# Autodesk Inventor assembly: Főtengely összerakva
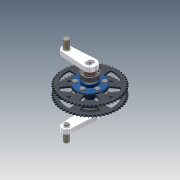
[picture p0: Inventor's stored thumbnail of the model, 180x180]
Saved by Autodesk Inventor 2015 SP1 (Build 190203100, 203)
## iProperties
Created: 2013-02
Part Number: Főtengely összerakva
Document SubType Name: Assembly
Designer: Marci
Author: Marci
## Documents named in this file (12)
- C:\Users\TREINA11\Desktop\#01- Polymechanics and Automation\01 - 3D Models\Pneumatic System\Főtengely összerakva.iam
- C:\Users\TREINA11\Desktop\#01- Polymechanics and Automation\01 - 3D Models\Pneumatic System\Főtengely.ipt
- C:\Users\TREINA11\Desktop\#01- Polymechanics and Automation\01 - 3D Models\Pneumatic System\Szabadonfutó távtartó.ipt
- C:\Users\TREINA11\Desktop\#01- Polymechanics and Automation\01 - 3D Models\Pneumatic System\inafag_hfl3030_elarmg9trzt6j3zc3til76m2w.iam
- C:\Users\TREINA11\Desktop\#01- Polymechanics and Automation\01 - 3D Models\Pneumatic System\DIN 471 - 30 x 1,5(1).ipt
- C:\Users\TREINA11\Desktop\#01- Polymechanics and Automation\01 - 3D Models\Pneumatic System\inafag_6205_1vmsegths975f8cvzct4fnofv.iam
- C:\Users\TREINA11\Desktop\#01- Polymechanics and Automation\01 - 3D Models\Pneumatic System\Sonka távtartó.ipt
- C:\Users\TREINA11\Desktop\#01- Polymechanics and Automation\01 - 3D Models\Pneumatic System\Sonka.ipt
- C:\Users\TREINA11\Desktop\#01- Polymechanics and Automation\01 - 3D Models\Pneumatic System\Csapszeg.ipt
- C:\Users\TREINA11\Desktop\#01- Polymechanics and Automation\01 - 3D Models\Pneumatic System\Csapszeg alátét.ipt
- C:\Users\TREINA11\Desktop\#01- Polymechanics and Automation\01 - 3D Models\Pneumatic System\Lánckerék összerakva.iam
- C:\Users\TREINA11\Desktop\#01- Polymechanics and Automation\01 - 3D Models\Pneumatic System\ISO 4017 - M8 x 16ISO.ipt
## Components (20 placed, 11 different names)
1. Főtengely:1 — Mate:1, Flush:1, Mate:2, Mate:3, Mate:6, Mate:7, Mate:8, Mate:9, Mate:10, Mate:11, Mate:12, Mate:13, Mate:14, Mate:16, Mate:35, Mate:36, Mate:38, Mate:39
2. Szabadonfutó távtartó:1 — Mate:1, Flush:1, Mate:4, Mate:5
3. inafag_hfl3030_elarmg9trzt6j3zc3til76m2w:1 [sub-assembly] — Mate:2, Mate:5, Mate:57, Flush:3
4. inafag_hfl3030_elarmg9trzt6j3zc3til76m2w:2 [sub-assembly] — Mate:3, Mate:4, Mate:58, Flush:4
5. DIN 471 > 9mm <= 300mm 30 x 1,5:1 — Mate:6, Mate:7
6. DIN 471 > 9mm <= 300mm 30 x 1,5:2 — Mate:8, Mate:9
7. inafag_6205_1vmsegths975f8cvzct4fnofv:1 [sub-assembly] — Mate:10, Mate:11, Mate:15
8. inafag_6205_1vmsegths975f8cvzct4fnofv:2 [sub-assembly] — Mate:12, Mate:13, Mate:17
9. Sonka távtartó:1 — Mate:14, Mate:15, Mate:37
10. Sonka távtartó:2 — Mate:16, Mate:17, Mate:40
11. Sonka:1 — Mate:35, Mate:36, Mate:37, Mate:51, Mate:52, Mate:53
12. Sonka:2 — Mate:38, Mate:39, Mate:40, Mate:45, Mate:46, Mate:47
13. Csapszeg:1 — Mate:45, Mate:46, Mate:48
14. ISO 4017 - M8 x 16ISO:1
15. Csapszeg alátét:1 — Mate:47, Mate:48
16. Csapszeg:2 — Mate:51, Mate:52, Mate:54
17. ISO 4017 - M8 x 16ISO:2
18. Csapszeg alátét:2 — Mate:53, Mate:54
19. Lánckerék összerakva:1 [sub-assembly] — Mate:57, Flush:3, Mate:59
20. Lánckerék összerakva:2 [sub-assembly] — Mate:58, Flush:4, Mate:59
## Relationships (37: Mate 34, Flush 3)
- Mate:1: Főtengely:1 ↔ Szabadonfutó távtartó:1
- Flush:1: Főtengely:1 ↔ Szabadonfutó távtartó:1
- Mate:2: Főtengely:1 ↔ inafag_hfl3030_elarmg9trzt6j3zc3til76m2w:1
- Mate:3: Főtengely:1 ↔ inafag_hfl3030_elarmg9trzt6j3zc3til76m2w:2
- Mate:4: Szabadonfutó távtartó:1 ↔ inafag_hfl3030_elarmg9trzt6j3zc3til76m2w:2
- Mate:5: Szabadonfutó távtartó:1 ↔ inafag_hfl3030_elarmg9trzt6j3zc3til76m2w:1
- Mate:6: Főtengely:1 ↔ DIN 471 > 9mm <= 300mm 30 x 1,5:1
- Mate:7: Főtengely:1 ↔ DIN 471 > 9mm <= 300mm 30 x 1,5:1
- Mate:8: Főtengely:1 ↔ DIN 471 > 9mm <= 300mm 30 x 1,5:2
- Mate:9: Főtengely:1 ↔ DIN 471 > 9mm <= 300mm 30 x 1,5:2
- Mate:10: Főtengely:1 ↔ inafag_6205_1vmsegths975f8cvzct4fnofv:1
- Mate:11: Főtengely:1 ↔ inafag_6205_1vmsegths975f8cvzct4fnofv:1
- Mate:12: Főtengely:1 ↔ inafag_6205_1vmsegths975f8cvzct4fnofv:2
- Mate:13: Főtengely:1 ↔ inafag_6205_1vmsegths975f8cvzct4fnofv:2
- Mate:14: Főtengely:1 ↔ Sonka távtartó:1
- Mate:15: inafag_6205_1vmsegths975f8cvzct4fnofv:1 ↔ Sonka távtartó:1
- Mate:16: Főtengely:1 ↔ Sonka távtartó:2
- Mate:17: inafag_6205_1vmsegths975f8cvzct4fnofv:2 ↔ Sonka távtartó:2
- Mate:35: Főtengely:1 ↔ Sonka:1
- Mate:36: Főtengely:1 ↔ Sonka:1
- Mate:37: Sonka távtartó:1 ↔ Sonka:1
- Mate:38: Főtengely:1 ↔ Sonka:2
- Mate:39: Főtengely:1 ↔ Sonka:2
- Mate:40: Sonka távtartó:2 ↔ Sonka:2
- Mate:45: Sonka:2 ↔ Csapszeg:1
- Mate:46: Sonka:2 ↔ Csapszeg:1
- Mate:47: Sonka:2 ↔ Csapszeg alátét:1
- Mate:48: Csapszeg:1 ↔ Csapszeg alátét:1
- Mate:51: Sonka:1 ↔ Csapszeg:2
- Mate:52: Sonka:1 ↔ Csapszeg:2
- Mate:53: Sonka:1 ↔ Csapszeg alátét:2
- Mate:54: Csapszeg:2 ↔ Csapszeg alátét:2
- Mate:57: inafag_hfl3030_elarmg9trzt6j3zc3til76m2w:1 ↔ Lánckerék összerakva:1
- Flush:3: inafag_hfl3030_elarmg9trzt6j3zc3til76m2w:1 ↔ Lánckerék összerakva:1
- Mate:58: inafag_hfl3030_elarmg9trzt6j3zc3til76m2w:2 ↔ Lánckerék összerakva:2
- Flush:4: inafag_hfl3030_elarmg9trzt6j3zc3til76m2w:2 ↔ Lánckerék összerakva:2
- Mate:59: Lánckerék összerakva:1 ↔ Lánckerék összerakva:2
